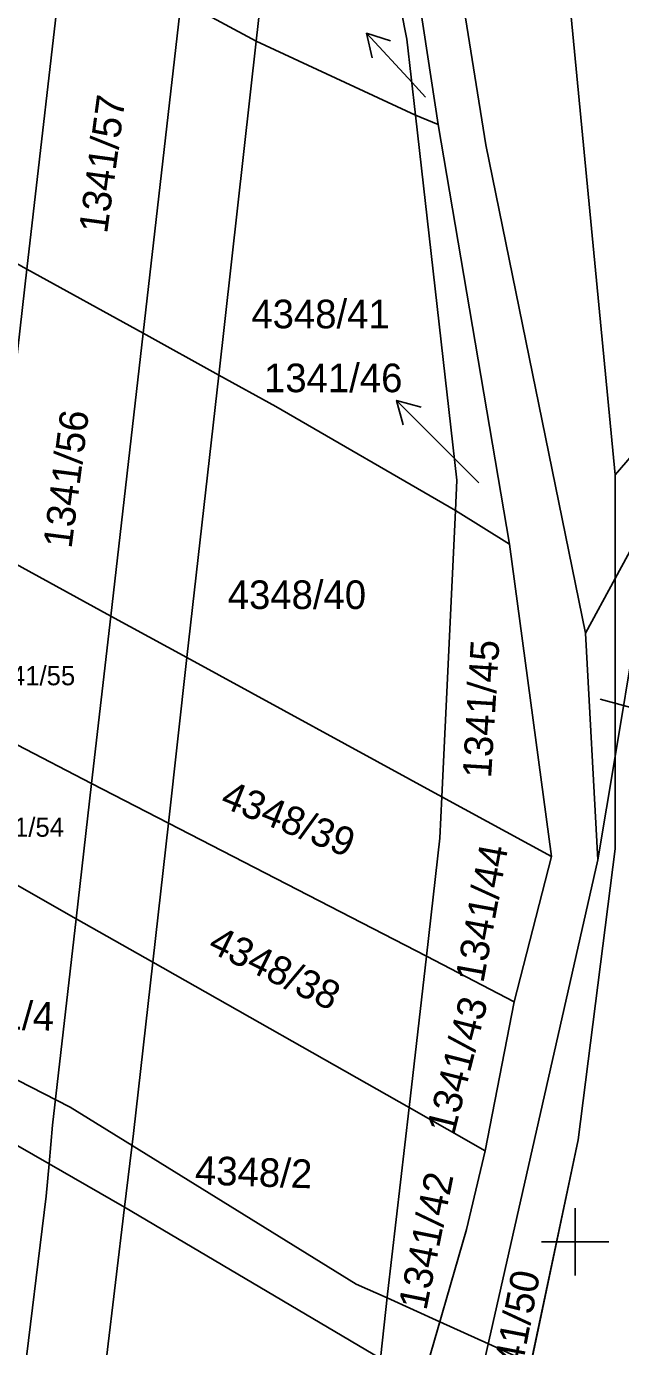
# Model space of a CAD drawing. Extents: x -735036 to -734743, y -1144813 to -1144181.
# Drawn here: x -734832.6 to -734797.3, y -1144606.2 to -1144527.8 of the extents above; entities that cross this region are included whole.
import ezdxf

# ---------------------------------------------------------------- set-up
doc = ezdxf.new("R2010")
doc.units = 0
for name, color, linetype in [('BPEJ', 7, 'Continuous'), ('Katastr_HRANICE DRÁHY', 7, 'Continuous'), ('Katastr_Hranice parcel', 7, 'Continuous'), ('Katastr_Parcelní čísla', 7, 'Continuous'), ('Katastr_Slučkované čáry', 7, 'Continuous'), ('Vrstva 7', 7, 'Continuous'), ('čtvercová síť', 7, 'Continuous')]:
    doc.layers.add(name, color=color, linetype=linetype)

# ---------------------------------------------------------------- blocks, each defined once
blk = doc.blocks.new('C691')
at = {"layer": 'Vrstva 7'}
for p, q in [((0, 0.5), (0, -0.5)), ((-0.5, 0), (0.5, 0))]:
    blk.add_line(p, q, dxfattribs=at)

msp = doc.modelspace()

# ---------------------------------------------------------------- linework, layer by layer
at = {"layer": 'BPEJ'}
msp.add_lwpolyline([(-734782.57, -1144536.98), (-734797.63, -1144554.43), (-734797.63, -1144560.59), (-734797.63, -1144571.16), (-734797.63, -1144576.65), (-734799.83, -1144593.94), (-734802.63, -1144607.21), (-734805.16, -1144606.06), (-734808.05, -1144604.75), (-734811.16, -1144603.33), (-734813, -1144602.5), (-734826.32, -1144594.27), (-734830, -1144592), (-734842.48, -1144585.59)], dxfattribs=at)
at = {"layer": 'Katastr_HRANICE DRÁHY'}
for points in [[(-734818.94, -1144528.67), (-734815.53, -1144498.35)], [(-734810.36, -1144526.75), (-734810.01, -1144528.54)], [(-734818.94, -1144528.67), (-734809.49, -1144533.07)], [(-734810.01, -1144528.54), (-734809.49, -1144533.07)], [(-734823.06, -1144565.29), (-734821.17, -1144548.5)], [(-734821.17, -1144548.5), (-734817.79, -1144550.37)], [(-734817.79, -1144550.37), (-734807.12, -1144556.54)], [(-734807.12, -1144556.54), (-734803.9, -1144558.55)], [(-734803.9, -1144558.55), (-734801.41, -1144577.1)], [(-734807.92, -1144573.55), (-734823.06, -1144565.29)], [(-734801.41, -1144577.1), (-734807.92, -1144573.55)]]:
    msp.add_lwpolyline(points, dxfattribs=at)
at = {"layer": 'Katastr_Hranice parcel'}
for points in [[(-734808.14, -1144533.62), (-734813.86, -1144496.12)], [(-734810.84, -1144500.3), (-734805.3, -1144534.82)], [(-734800.88, -1144520.61), (-734797.63, -1144554.43)], [(-734823.4, -1144526.26), (-734818.94, -1144528.67)], [(-734821.17, -1144548.5), (-734818.94, -1144528.67)], [(-734809.49, -1144533.07), (-734807.03, -1144554.74)], [(-734808.14, -1144533.62), (-734809.49, -1144533.07)], [(-734803.9, -1144558.55), (-734808.14, -1144533.62)], [(-734805.3, -1144534.82), (-734799.39, -1144563.84)], [(-734797.63, -1144554.43), (-734782.57, -1144536.98)], [(-734836.63, -1144539.96), (-734832.56, -1144542.21)], [(-734832.56, -1144542.21), (-734825.66, -1144546.02)], [(-734825.66, -1144546.02), (-734821.17, -1144548.5)], [(-734797.63, -1144560.59), (-734791.08, -1144548.5)], [(-734797.63, -1144560.59), (-734797.63, -1144554.43)], [(-734807.03, -1144554.74), (-734807.12, -1144556.54)], [(-734807.12, -1144556.54), (-734807.92, -1144573.55)], [(-734827.58, -1144562.82), (-734834.48, -1144559.05)], [(-734799.39, -1144563.84), (-734797.63, -1144560.59)], [(-734797.63, -1144571.16), (-734797.63, -1144560.59)], [(-734823.06, -1144565.29), (-734827.58, -1144562.82)], [(-734799.39, -1144563.84), (-734798.65, -1144577.31)], [(-734796.42, -1144563.87), (-734797.63, -1144571.16)], [(-734824.16, -1144575.12), (-734823.06, -1144565.29)], [(-734828.72, -1144572.76), (-734833.15, -1144570.47)], [(-734797.63, -1144571.16), (-734798.65, -1144577.31)], [(-734797.63, -1144576.65), (-734797.63, -1144571.16)], [(-734824.16, -1144575.12), (-734828.72, -1144572.76)], [(-734807.92, -1144573.55), (-734808.04, -1144576.02)], [(-734825.09, -1144583.38), (-734824.16, -1144575.12)], [(-734808.84, -1144583.03), (-734824.16, -1144575.12)], [(-734808.04, -1144576.02), (-734808.84, -1144583.03)], [(-734829.64, -1144580.8), (-734836.52, -1144576.89)], [(-734798.65, -1144577.31), (-734805.94, -1144609.48)], [(-734803.62, -1144585.73), (-734801.41, -1144577.1)], [(-734799.83, -1144593.94), (-734797.63, -1144576.65)], [(-734825.09, -1144583.38), (-734829.64, -1144580.8)], [(-734826.23, -1144593.55), (-734825.09, -1144583.38)], [(-734809.87, -1144592.02), (-734825.09, -1144583.38)], [(-734808.84, -1144583.03), (-734809.87, -1144592.02)], [(-734803.62, -1144585.73), (-734808.84, -1144583.03)], [(-734805.34, -1144594.59), (-734803.62, -1144585.73)], [(-734838.18, -1144591.38), (-734831.24, -1144595.37)], [(-734809.87, -1144592.02), (-734811.14, -1144603.11)], [(-734805.34, -1144594.59), (-734809.87, -1144592.02)], [(-734826.76, -1144597.94), (-734826.23, -1144593.55)], [(-734814.3, -1144662.64), (-734799.83, -1144593.94)], [(-734806.45, -1144599.27), (-734805.34, -1144594.59)], [(-734831.24, -1144595.37), (-734826.76, -1144597.94)], [(-734826.76, -1144597.94), (-734828.38, -1144611.37)], [(-734811.57, -1144606.92), (-734826.76, -1144597.94)], [(-734809.1, -1144608.38), (-734806.45, -1144599.27)], [(-734811.14, -1144603.11), (-734811.57, -1144606.92)]]:
    msp.add_lwpolyline(points, dxfattribs=at)
at = {"layer": 'Katastr_Parcelní čísla'}
for p, q in [((-734812.064, -1144529.657), (-734812.396, -1144528.193)), ((-734808.89, -1144531.99), (-734809.68, -1144531.13)), ((-734810.22, -1144551.461), (-734810.608, -1144550.012)), ((-734805.72, -1144554.9), (-734807.78, -1144552.84)), ((-734798.51, -1144567.759), (-734795.13, -1144568.679))]:
    msp.add_line(p, q, dxfattribs=at)
for points in [[(-734809.68, -1144531.13), (-734812.396, -1144528.193), (-734810.963, -1144528.639)], [(-734807.78, -1144552.84), (-734810.608, -1144550.012), (-734809.159, -1144550.4)]]:
    msp.add_lwpolyline(points, dxfattribs=at)
at = {"layer": 'Katastr_Slučkované čáry'}
for points in [[(-734830.38, -1144523.1), (-734832.56, -1144542.21)], [(-734823.4, -1144526.26), (-734825.66, -1144546.02)], [(-734832.56, -1144542.21), (-734834.48, -1144559.05)], [(-734825.66, -1144546.02), (-734827.58, -1144562.82)], [(-734827.58, -1144562.82), (-734828.72, -1144572.76)], [(-734828.72, -1144572.76), (-734829.64, -1144580.8)], [(-734829.64, -1144580.8), (-734831.04, -1144593.06)], [(-734831.04, -1144593.06), (-734831.24, -1144595.37)], [(-734831.24, -1144595.37), (-734831.41, -1144597.28)], [(-734831.41, -1144597.28), (-734832.82, -1144608.77)]]:
    msp.add_lwpolyline(points, dxfattribs=at)

# ---------------------------------------------------------------- block references
at = {"layer": 'čtvercová síť', "xscale": 4, "yscale": 4}
msp.add_blockref('C691', (-734800, -1144600), dxfattribs=at)

# ---------------------------------------------------------------- texts
at = {"layer": 'Katastr_Parcelní čísla'}
for s, rotation, p in [('1341/57', 82.29411, (-734827.803, -1144540.14)), ('1341/56', 82.69425, (-734829.917, -1144558.849)), ('1341/45', 86.52627, (-734804.997, -1144572.483)), ('4348/39', 338.08932, (-734821.153, -1144574.111)), ('1341/44', 79.64415, (-734805.458, -1144584.662)), ('4348/38', 333.99027, (-734821.895, -1144582.69)), ('1341/4', 358.29018, (-734837.921, -1144587.244)), ('1341/43', 75.79134, (-734807.192, -1144593.672)), ('4348/2', 358.03449, (-734822.6, -1144596.578)), ('1341/42', 78.58224, (-734808.845, -1144604.121)), ('1341/50', 79.13709, (-734803.622, -1144609.95))]:
    msp.add_text(s, height=1.7, rotation=rotation, dxfattribs=at).set_placement(p)
for s, height, p in [('4348/41', 1.7, (-734819.234, -1144545.723)), ('1341/46', 1.7, (-734818.481, -1144549.52)), ('4348/40', 1.7, (-734820.637, -1144562.4)), ('1341/55', 1.14, (-734835.206, -1144566.93)), ('1341/54', 1.14, (-734835.869, -1144575.93))]:
    msp.add_text(s, height=height, dxfattribs=at).set_placement(p)

doc.saveas('drawing.dxf')
